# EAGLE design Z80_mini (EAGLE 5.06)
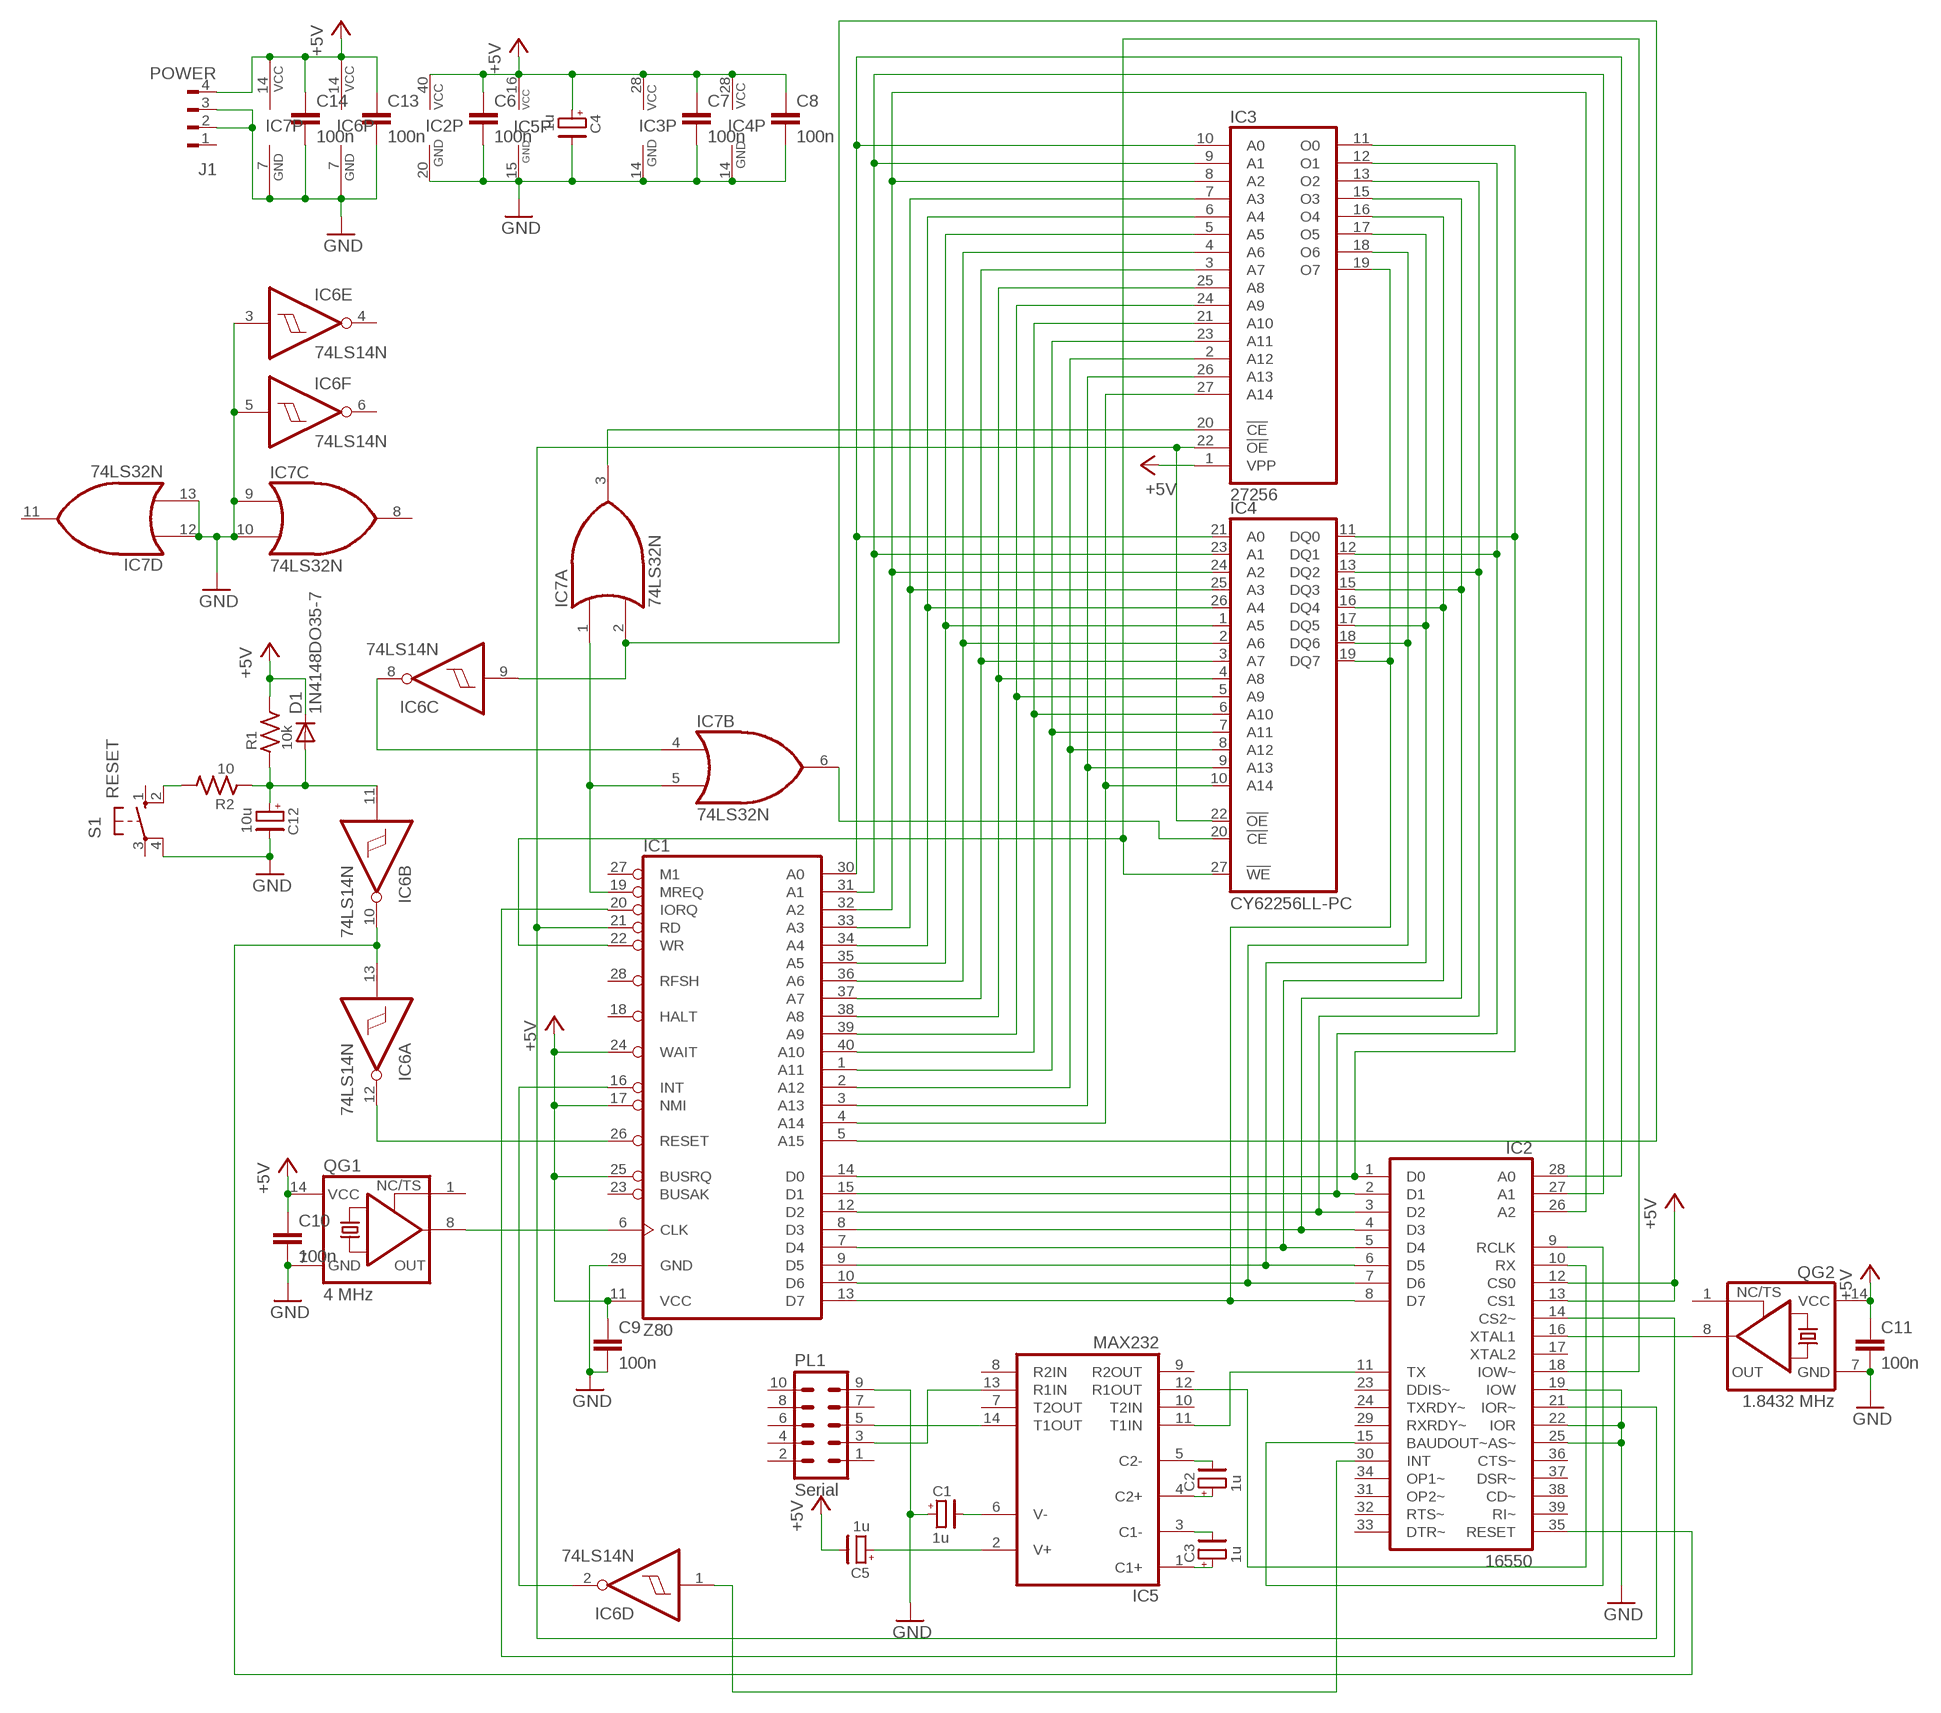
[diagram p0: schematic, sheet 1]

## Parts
C1  1u  CE01A  [CE01A]
C2  1u  CE01A  [CE01A]
C3  1u  CE01A  [CE01A]
C4  1u  CE01A  [CE01A]
C5  1u  CE01A  [CE01A]
C6  100n  C5/2.5  [C5B2.5]
C7  100n  C5/2.5  [C5B2.5]
C8  100n  C5/2.5  [C5B2.5]
C9  100n  C5/2.5  [C5B2.5]
C10  100n  C5/2.5  [C5B2.5]
C11  100n  C5/2.5  [C5B2.5]
C12  10u  CE01A  [CE01A]
C13  100n  C5/2.5  [C5B2.5]
C14  100n  C5/2.5  [C5B2.5]
D1  1N4148DO35-7  [DO35-7]
IC1  Z80  Z80CPU  [DIL40]
IC2  16550  XR-16C550P  [DIL40]
IC3  27256  [DIL28]
IC4  CY62256LL-PC  [DIL28-6]
IC5  MAX232  [DIL16]
IC6  74LS14N  [DIL14]
IC7  74LS32N  [DIL14]
J1  POWER  FLOPPY-4  [FLOPPY-4]
PL1  Serial  10H  [10H]
QG1  4 MHz  XO-14  [DIL14S]
QG2  1.8432 MHz  XO-14  [DIL14S]
R1  10k  RU  [R04N]
R2  10  RU  [R04N]
S1  RESET  10-XX  [B3F-10XX]

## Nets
+5V: C4.+ C5.- C6.1 C7.1 C8.1 C9.1 C10.1 C11.1 C13.1 C14.1 D1.C IC1.11(VCC) IC1.17(NMI) IC1.24(WAIT) IC1.25(BUSRQ) IC2.12(CS0) IC2.13(CS1) IC2.40(VCC) IC3.1(VPP) IC3.28(VCC) IC4.28(VCC) IC5.16(VCC) IC6.14(P:VCC) IC7.14(P:VCC) J1.4 QG1.14(VCC) QG2.14(VCC) R1.2
GND: C1.+ C4.- C6.2 C7.2 C8.2 C9.2 C10.2 C11.2 C12.- C13.2 C14.2 IC1.29(GND) IC2.19(IOW) IC2.20(GND) IC2.22(IOR) IC2.25(AS~) IC3.14(GND) IC4.14(GND) IC5.15(GND) IC6.3(E:I) IC6.5(F:I) IC6.7(P:GND) IC7.7(P:GND) IC7.9(C:I0) IC7.10(C:I1) IC7.12(D:I0) IC7.13(D:I1) J1.2 J1.3 PL1.9 QG1.7(GND) QG2.7(GND) S1.4(P1)
N$1: IC1.14(D0) IC2.1(D0) IC3.11(O0) IC4.11(DQ0)
N$2: IC1.15(D1) IC2.2(D1) IC3.12(O1) IC4.12(DQ1)
N$3: IC1.12(D2) IC2.3(D2) IC3.13(O2) IC4.13(DQ2)
N$4: IC1.8(D3) IC2.4(D3) IC3.15(O3) IC4.15(DQ3)
N$5: IC1.7(D4) IC2.5(D4) IC3.16(O4) IC4.16(DQ4)
N$6: IC1.9(D5) IC2.6(D5) IC3.17(O5) IC4.17(DQ5)
N$7: IC1.10(D6) IC2.7(D6) IC3.18(O6) IC4.18(DQ6)
N$8: IC1.13(D7) IC2.8(D7) IC3.19(O7) IC4.19(DQ7)
N$9: IC1.30(A0) IC2.28(A0) IC3.10(A0) IC4.21(A0)
N$10: IC1.31(A1) IC2.27(A1) IC3.9(A1) IC4.23(A1)
N$11: IC1.32(A2) IC2.26(A2) IC3.8(A2) IC4.24(A2)
N$12: IC1.33(A3) IC3.7(A3) IC4.25(A3)
N$13: IC1.34(A4) IC3.6(A4) IC4.26(A4)
N$14: IC1.35(A5) IC3.5(A5) IC4.1(A5)
N$15: IC1.36(A6) IC3.4(A6) IC4.2(A6)
N$16: IC1.37(A7) IC3.3(A7) IC4.3(A7)
N$17: IC1.38(A8) IC3.25(A8) IC4.4(A8)
N$18: IC1.39(A9) IC3.24(A9) IC4.5(A9)
N$19: IC1.40(A10) IC3.21(A10) IC4.6(A10)
N$20: IC1.1(A11) IC3.23(A11) IC4.7(A11)
N$21: IC1.2(A12) IC3.2(A12) IC4.8(A12)
N$22: IC1.3(A13) IC3.26(A13) IC4.9(A13)
N$23: IC1.4(A14) IC3.27(A14) IC4.10(A14)
N$24: IC2.11(TX) IC5.11(T1IN)
N$25: IC1.21(RD) IC2.21(IOR~) IC3.22(!OE) IC4.22(!OE)
N$26: IC1.22(WR) IC2.18(IOW~) IC4.27(!WE)
N$27: IC2.10(RX) IC5.12(R1OUT)
N$28: C1.- IC5.6(V-)
N$29: C2.- IC5.5(C2-)
N$30: C2.+ IC5.4(C2+)
N$31: C3.- IC5.3(C1-)
N$32: C3.+ IC5.1(C1+)
N$33: C5.+ IC5.2(V+)
N$34: IC5.14(T1OUT) PL1.5
N$35: IC5.13(R1IN) PL1.3
N$36: IC1.6(CLK) QG1.8(OUT)
N$37: IC1.26(RESET) IC6.12(A:O)
N$38: IC2.16(XTAL1) QG2.8(OUT)
N$39: IC2.9(RCLK) IC2.15(BAUDOUT~)
N$40: IC1.20(IORQ) IC2.14(CS2~)
N$41: IC2.35(RESET) IC6.10(B:O) IC6.13(A:I)
N$42: C12.+ D1.A IC6.11(B:I) R1.1 R2.1
N$43: R2.2 S1.2(S1)
N$44: IC1.19(MREQ) IC7.1(A:I0) IC7.5(B:I1)
N$46: IC3.20(!CE) IC7.3(A:O)
N$47: IC6.8(C:O) IC7.4(B:I0)
N$48: IC4.20(!CE) IC7.6(B:O)
N$49: IC2.30(INT) IC6.1(D:I)
N$50: IC1.16(INT) IC6.2(D:O)
N$52: IC1.5(A15) IC6.9(C:I) IC7.2(A:I1)
Unconnected: IC1.18(HALT) IC1.23(BUSAK) IC1.27(M1) IC1.28(RFSH) IC2.17(XTAL2) IC2.23(DDIS~) IC2.24(TXRDY~) IC2.29(RXRDY~) IC2.31(OP2~) IC2.32(RTS~) IC2.33(DTR~) IC2.34(OP1~) IC2.36(CTS~) IC2.37(DSR~) IC2.38(CD~) IC2.39(RI~) IC5.7(T2OUT) IC5.8(R2IN) IC5.9(R2OUT) IC5.10(T2IN) IC6.4(E:O) IC6.6(F:O) IC7.8(C:O) IC7.11(D:O) J1.1 PL1.1 PL1.2 PL1.4 PL1.6 PL1.7 PL1.8 PL1.10 QG1.1(TS) QG2.1(TS) S1.1(S) S1.3(P)

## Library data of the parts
C1-C5 C12 = divers:CE: Electrolytic capacitor
C6-C11 C13 C14 = capacitor-wima:C: CAPACITOR
D1 = diode:1N4148: DIODE
IC1 = zilog:Z80CPU: Z80 FAMILY DEVICE
IC2 = exar:XR-16C550P: UART/FIFO
IC3 = memory:27256: MEMORY
IC4 = memory-sram:CY62256LL-?*: 256K (32K x 8) CMOS-Static RAM Source: http://download.cypress.com.edgesuite.net/design_resources/datasheets/contents/cy62256_8.pdf
IC5 = maxim:MAX232: RS232 TRANSEIVER
IC6 = 74xx-us:74*14: Hex schmitt trigger INVERTER
IC7 = 74xx-us:74*32: Quad 2-input OR gate
J1 = con-amp:FLOPPY-4: MATE N-LOCK Floppy / HDD conector Distributor: Bürklin 71F970
PL1 = con-harting-h:10H: CONNECTOR
QG1 QG2 = crystal:XO-: CRYSTAL
R1 R2 = divers:RU: Resistor, US symbol
S1 = switch-omron:10-XX: OMRON SWITCH

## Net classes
0 +5V: width 0.508 mm

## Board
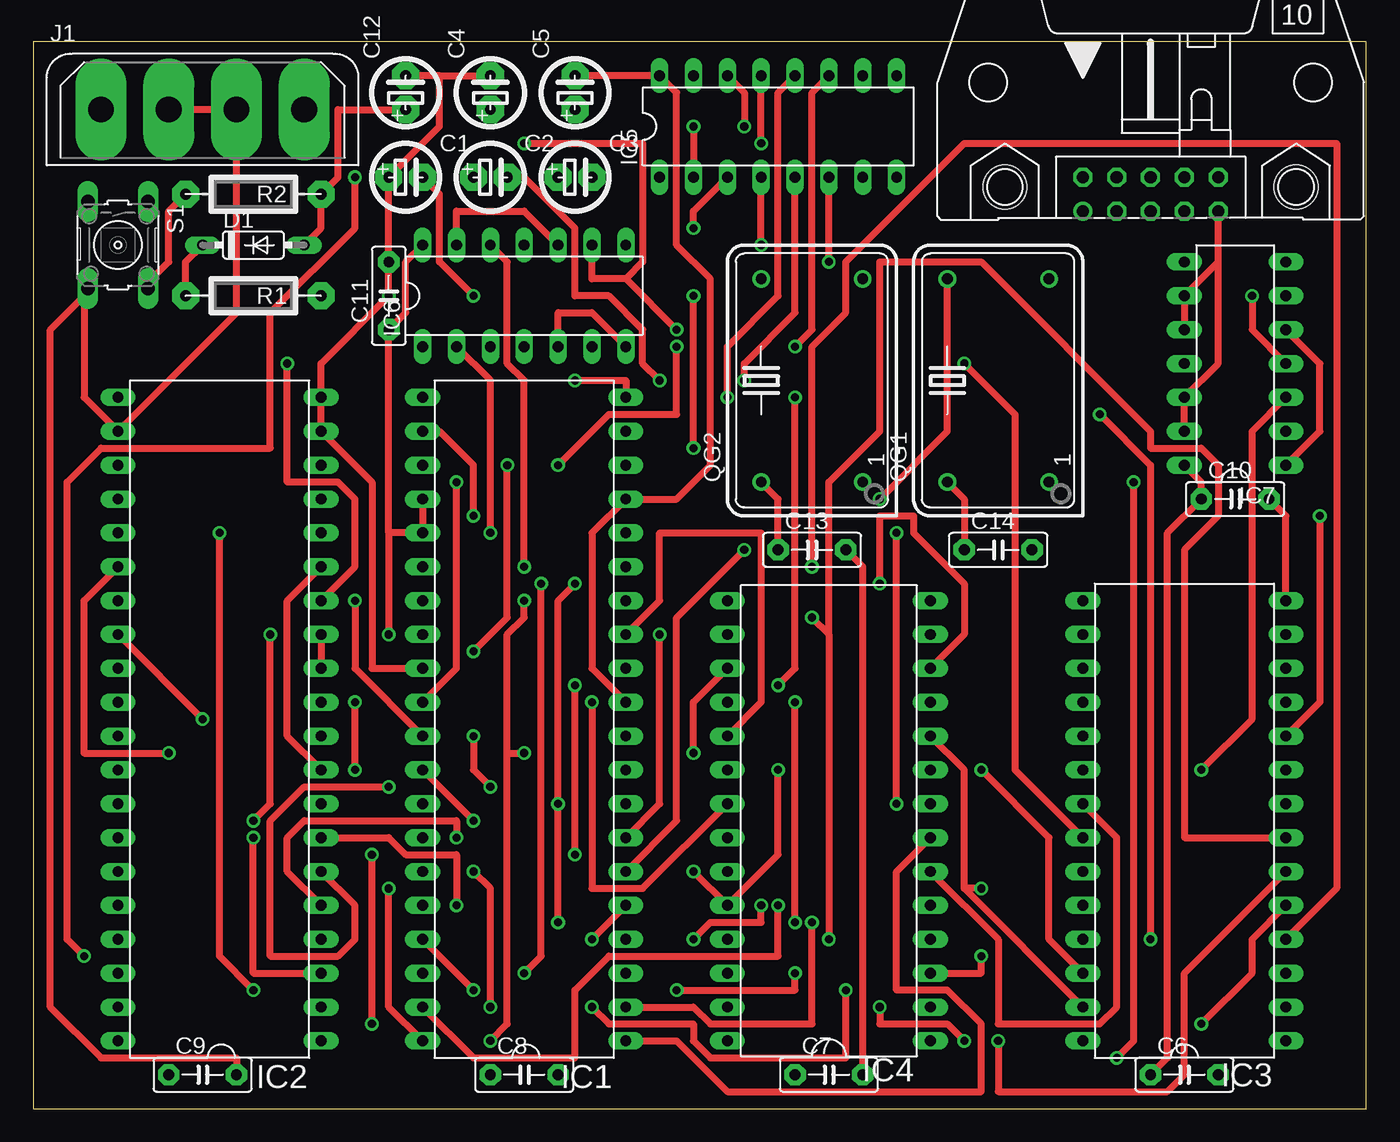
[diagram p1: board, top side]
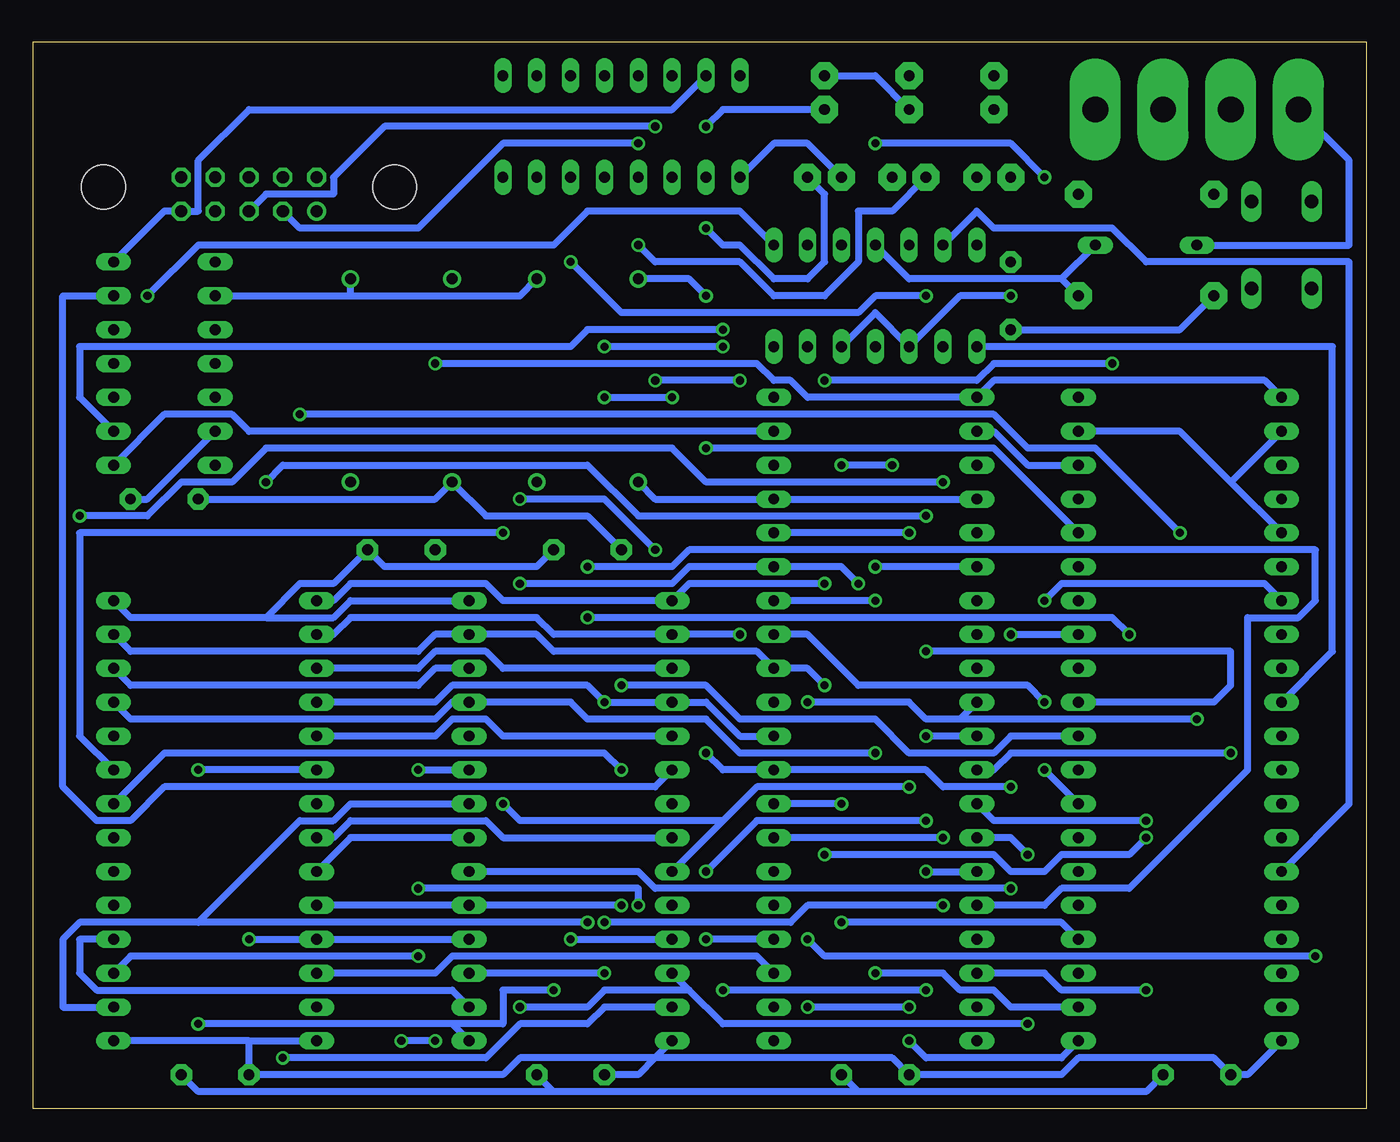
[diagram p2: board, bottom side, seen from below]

Size 100 x 80 mm. Coordinates in mm from the lower left corner, seen from the top.
Outline: 0,0 100,0 100,80 0,80 0,0
Copper layers (1*16): Top 0.035mm / dielectric 1.5mm / Bottom 0.035mm
Design rules "default *": minimum track width 20mil, minimum drill 24mil, track to track 8mil, track to pad 8mil, pad to pad 8mil, via to via 8mil, smd to smd 8mil, copper to edge 40mil, drill to drill 8mil, minimum pad ring 10mil, minimum via ring 8mil, stop-mask expansion 4mil, vias tented up to drill 0mil, thermal gap 10mil

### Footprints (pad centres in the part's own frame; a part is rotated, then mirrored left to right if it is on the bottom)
CE01A = drill 0.813 pad 2.032 octagon: + -1.27,0; - 1.27,0
C5B2.5 = drill 0.813 pad 1.6 octagon: 1 -2.54,0; 2 2.54,0
DO35-7 = drill 0.813 long: A 3.81,0; C -3.81,0
DIL40 = drill 0.813 long: 1 -24.13,-7.62; 2 -21.59,-7.62; 3 -19.05,-7.62; 4 -16.51,-7.62; 5 -13.97,-7.62; 6 -11.43,-7.62; 7 -8.89,-7.62; 8 -6.35,-7.62; 9 -3.81,-7.62; 10 -1.27,-7.62; 11 1.27,-7.62; 12 3.81,-7.62; 13 6.35,-7.62; 14 8.89,-7.62; 15 11.43,-7.62; 16 13.97,-7.62; 17 16.51,-7.62; 18 19.05,-7.62; 19 21.59,-7.62; 20 24.13,-7.62; 21 24.13,7.62; 22 21.59,7.62; 23 19.05,7.62; 24 16.51,7.62; 25 13.97,7.62; 26 11.43,7.62; 27 8.89,7.62; 28 6.35,7.62; 29 3.81,7.62; 30 1.27,7.62; 31 -1.27,7.62; 32 -3.81,7.62; 33 -6.35,7.62; 34 -8.89,7.62; 35 -11.43,7.62; 36 -13.97,7.62; 37 -16.51,7.62; 38 -19.05,7.62; 39 -21.59,7.62; 40 -24.13,7.62
DIL28 = drill 0.813 long: 1 -16.51,-7.62; 2 -13.97,-7.62; 3 -11.43,-7.62; 4 -8.89,-7.62; 5 -6.35,-7.62; 6 -3.81,-7.62; 7 -1.27,-7.62; 8 1.27,-7.62; 9 3.81,-7.62; 10 6.35,-7.62; 11 8.89,-7.62; 12 11.43,-7.62; 13 13.97,-7.62; 14 16.51,-7.62; 15 16.51,7.62; 16 13.97,7.62; 17 11.43,7.62; 18 8.89,7.62; 19 6.35,7.62; 20 3.81,7.62; 21 1.27,7.62; 22 -1.27,7.62; 23 -3.81,7.62; 24 -6.35,7.62; 25 -8.89,7.62; 26 -11.43,7.62; 27 -13.97,7.62; 28 -16.51,7.62
DIL28-6 = drill 0.813 long: 1 -16.51,-7.62; 2 -13.97,-7.62; 3 -11.43,-7.62; 4 -8.89,-7.62; 5 -6.35,-7.62; 6 -3.81,-7.62; 7 -1.27,-7.62; 8 1.27,-7.62; 9 3.81,-7.62; 10 6.35,-7.62; 11 8.89,-7.62; 12 11.43,-7.62; 13 13.97,-7.62; 14 16.51,-7.62; 15 16.51,7.62; 16 13.97,7.62; 17 11.43,7.62; 18 8.89,7.62; 19 6.35,7.62; 20 3.81,7.62; 21 1.27,7.62; 22 -1.27,7.62; 23 -3.81,7.62; 24 -6.35,7.62; 25 -8.89,7.62; 26 -11.43,7.62; 27 -13.97,7.62; 28 -16.51,7.62
DIL16 = drill 0.813 long: 1 -8.89,-3.81; 2 -6.35,-3.81; 3 -3.81,-3.81; 4 -1.27,-3.81; 5 1.27,-3.81; 6 3.81,-3.81; 7 6.35,-3.81; 8 8.89,-3.81; 9 8.89,3.81; 10 6.35,3.81; 11 3.81,3.81; 12 1.27,3.81; 13 -1.27,3.81; 14 -3.81,3.81; 15 -6.35,3.81; 16 -8.89,3.81
DIL14 = drill 0.813 long: 1 -7.62,-3.81; 2 -5.08,-3.81; 3 -2.54,-3.81; 4 0,-3.81; 5 2.54,-3.81; 6 5.08,-3.81; 7 7.62,-3.81; 8 7.62,3.81; 9 5.08,3.81; 10 2.54,3.81; 11 0,3.81; 12 -2.54,3.81; 13 -5.08,3.81; 14 -7.62,3.81
FLOPPY-4 = drill 1.93 pad 3.81 long: 1 7.62,0; 2 2.54,0; 3 -2.54,0; 4 -7.62,0
10H = drill 0.914 round: 1 -5.08,-1.27 | drill 0.914 octagon: 2 -5.08,1.27; 3 -2.54,-1.27; 4 -2.54,1.27; 5 0,-1.27; 6 0,1.27; 7 2.54,-1.27; 8 2.54,1.27; 9 5.08,-1.27; 10 5.08,1.27 | hole 3.302: -10.922,0.533; 10.922,0.533
DIL14S = drill 0.813 round: 1 -7.62,-3.81; 7 7.62,-3.81; 8 7.62,3.81; 14 -7.62,3.81
R04N = drill 0.813 pad 2.032 octagon: 1 -5.08,0; 2 5.08,0
B3F-10XX = drill 1.016 long: 1 -3.251,2.261; 2 3.251,2.261; 3 -3.251,-2.261; 4 3.251,-2.261

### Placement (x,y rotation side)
C1  27.94,69.85 0 top
C2  34.29,69.85 0 top
C3  40.64,69.85 0 top
C4  34.29,76.2 90 top
C5  40.64,76.2 90 top
C6  86.36,2.54 0 top
C7  59.69,2.54 0 top
C8  36.83,2.54 0 top
C9  12.7,2.54 0 top
C10  90.17,45.72 0 top
C11  26.67,60.96 90 top
C12  27.94,76.2 90 top
C13  58.42,41.91 0 top
C14  72.39,41.91 0 top
D1  16.51,64.77 0 top
IC1  36.83,29.21 90 top
IC2  13.97,29.21 90 top
IC3  86.36,21.59 90 top
IC4  59.69,21.59 90 top
IC5  55.88,73.66 0 top
IC6  36.83,60.96 0 top
IC7  90.17,55.88 90 top
J1  12.7,74.93 0 top
PL1  83.82,68.58 0 top
QG1  72.39,54.61 90 top
QG2  58.42,54.61 90 top
R1  16.51,60.96 180 top
R2  16.51,68.58 180 top
S1  6.35,64.77 270 top

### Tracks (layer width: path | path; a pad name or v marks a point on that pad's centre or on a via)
+5V  (via drill 0.61)
  Top 0.508: D1.C 11.43,63.5 R1.2 | IC1.24 IC1.25 26.67,43.18 | IC2.13 IC2.12 | IC6.14 27.94,63.5 27.94,59.69 C11.1 26.67,43.18 | 26.67,43.18 v26.67,35.56 | IC7.14 87.63,46.99 C10.1 85.09,43.18 85.09,3.81 C6.1 | QG1.14 69.85,45.72 C14.1 | C5.- IC5.16 48.26,76.2 48.26,64.77 50.8,62.23 50.8,48.26 48.26,45.72 IC1.17 41.91,43.18 41.91,33.02 IC1.11 | QG2.14 55.88,45.72 C13.1
  Bottom 0.508: 83.82,5.08 IC3.1 | 83.82,5.08 IC3.28 | 83.82,5.08 C6.1 64.77,2.54 63.5,3.81 53.34,3.81 | IC2.40 8.89,2.54 C9.1 11.43,3.81 21.59,3.81 22.86,2.54 C8.1 35.56,3.81 53.34,3.81 | 53.34,3.81 54.61,2.54 C7.1 | 53.34,3.81 IC4.28 | v26.67,35.56 IC2.13 | R1.2 13.97,58.42 C11.1 | J1.4 1.27,71.12 1.27,64.77 D1.C | C10.1 69.85,45.72 QG1.14 66.04,44.45 58.42,44.45 C13.1 | C4.+ 36.83,77.47 C5.- | QG2.14 53.34,45.72 IC1.17 IC1.24
GND  (via drill 0.61)
  Top 0.508: IC6.7 41.91,59.69 39.37,59.69 IC6.5 | 30.48,77.47 C4.- | 30.48,77.47 C12.- | 30.48,77.47 30.48,73.66 C1.+ C11.2 v26.67,60.96 21.59,55.88 IC2.20 IC2.19 25.4,46.99 25.4,33.02 IC1.29 | J1.3 J1.2 15.24,59.69 IC2.22 3.81,53.34 3.81,60.96 | IC7.13 IC7.12 88.9,55.88 88.9,63.5 | C10.2 93.98,44.45 IC3.14 | IC7.10 IC7.9 88.9,63.5 | 88.9,63.5 PL1.9 | C7.2 62.23,40.64 C13.2 | 3.81,60.96 1.27,58.42 1.27,7.62 5.08,3.81 15.24,3.81 C9.2 | 3.81,60.96 S1.4
  Bottom 0.508: IC6.5 36.83,59.69 IC6.3 30.48,60.96 v26.67,60.96 | 10.16,46.99 13.97,50.8 IC2.19 | 10.16,46.99 IC2.25 | IC2.22 10.16,46.99 | C9.2 16.51,1.27 38.1,1.27 | 38.1,1.27 C8.2 | 60.96,1.27 C7.2 | 38.1,1.27 60.96,1.27 | C6.2 87.63,1.27 60.96,1.27 | C13.2 62.23,40.64 73.66,40.64 C14.2 77.47,39.37 80.01,39.37 82.55,36.83 | IC4.14 76.2,38.1 77.47,36.83 82.55,36.83 | 82.55,36.83 92.71,36.83 IC3.14 | IC7.13 91.44,45.72 C10.2 | QG2.7 63.5,60.96 76.2,60.96 | IC7.9 76.2,60.96 | 76.2,60.96 QG1.7 | IC7.7 90.17,67.31 PL1.9 87.63,67.31 87.63,71.12 83.82,74.93 52.07,74.93 IC5.15
N$1  (via drill 0.61)
  Top 0.508: v34.29,5.08 35.56,6.35 35.56,26.67 | 35.56,26.67 35.56,35.56 36.83,36.83 v36.83,38.1 | 35.56,26.67 v36.83,26.67
  Bottom 0.508: IC3.11 92.71,29.21 69.85,29.21 68.58,30.48 IC4.11 59.69,30.48 58.42,29.21 49.53,29.21 46.99,26.67 v36.83,26.67 | IC2.1 22.86,3.81 33.02,3.81 v34.29,5.08 | v36.83,38.1 IC1.14
N$2  (via drill 0.61)
  Top 0.508: v36.83,10.16 38.1,11.43 v38.1,39.37 | IC4.12 69.85,35.56 69.85,39.37 66.04,43.18 66.04,44.45 63.5,44.45 v63.5,39.37
  Bottom 0.508: IC4.12 69.85,33.02 71.12,31.75 92.71,31.75 IC3.12 | IC2.2 26.67,7.62 27.94,8.89 30.48,8.89 31.75,10.16 v36.83,10.16 | v38.1,39.37 39.37,40.64 IC1.15 50.8,40.64 52.07,39.37 v63.5,39.37
N$3  (via drill 0.61)
  Top 0.508: IC2.3 16.51,10.16 v16.51,20.32 | v40.64,19.05 v40.64,31.75
  Bottom 0.508: v16.51,20.32 17.78,19.05 22.86,19.05 24.13,17.78 26.67,17.78 27.94,19.05 v40.64,19.05 | v40.64,31.75 41.91,33.02 IC1.12 45.72,34.29 60.96,34.29 62.23,35.56 IC4.13 69.85,35.56 71.12,34.29 92.71,34.29 IC3.13
N$4  (via drill 0.61)
  Top 0.508: v39.37,13.97 v39.37,22.86 39.37,38.1 v40.64,39.37
  Bottom 0.508: IC3.15 77.47,38.1 76.2,39.37 66.04,39.37 64.77,38.1 IC4.15 50.8,39.37 v40.64,39.37 | IC2.4 22.86,13.97 v39.37,13.97 | v39.37,22.86 IC1.8
N$5  (via drill 0.61)
  Top 0.508: IC2.5 19.05,17.78 19.05,20.32 20.32,21.59 31.75,21.59 v31.75,20.32 | v46.99,35.56 46.99,22.86 IC1.7
  Bottom 0.508: IC3.16 77.47,35.56 76.2,36.83 62.23,36.83 60.96,35.56 IC4.16 v46.99,35.56 | v31.75,20.32 IC1.7
N$6  (via drill 0.61)
  Top 0.508: IC2.6 24.13,15.24 24.13,12.7 22.86,11.43 17.78,11.43 17.78,21.59 20.32,24.13 v26.67,24.13 | IC4.17 49.53,30.48 v49.53,26.67
  Bottom 0.508: IC4.17 64.77,33.02 66.04,34.29 69.85,34.29 71.12,33.02 IC3.17 | v26.67,24.13 31.75,24.13 33.02,25.4 IC1.9 48.26,25.4 v49.53,26.67
N$7  (via drill 0.61)
  Top 0.508: IC2.7 26.67,20.32 27.94,19.05 31.75,19.05 v31.75,15.24 | v57.15,13.97 v57.15,30.48
  Bottom 0.508: v31.75,15.24 41.91,15.24 43.18,13.97 v57.15,13.97 | IC1.10 46.99,27.94 49.53,30.48 IC4.18 v57.15,30.48 58.42,31.75 68.58,31.75 69.85,30.48 IC3.18
N$8  (via drill 0.61)
  Top 0.508: v24.13,25.4 v24.13,30.48 | IC4.19 54.61,30.48 54.61,43.18 46.99,43.18 46.99,38.1 IC1.13
  Bottom 0.508: IC4.19 64.77,27.94 66.04,29.21 68.58,29.21 69.85,27.94 IC3.19 | IC2.8 v24.13,25.4 | v24.13,30.48 25.4,31.75 38.1,31.75 41.91,35.56 IC1.13
N$9  (via drill 0.61)
  Top 0.508: IC4.21 45.72,16.51 41.91,16.51 v41.91,30.48 | IC2.28 v12.7,29.21 | IC3.10 96.52,30.48 v96.52,44.45 | v31.75,46.99 31.75,33.02 IC1.30
  Bottom 0.508: v41.91,30.48 34.29,30.48 33.02,29.21 30.48,29.21 | 30.48,29.21 IC1.30 | v12.7,29.21 30.48,29.21 | v96.52,44.45 91.44,44.45 88.9,46.99 85.09,46.99 82.55,49.53 52.07,49.53 49.53,46.99 v31.75,46.99
N$10  (via drill 0.61)
  Top 0.508: IC1.31 24.13,33.02 v24.13,38.1 | v34.29,24.13 33.02,25.4 v33.02,27.94 | v64.77,22.86 v64.77,43.18
  Bottom 0.508: v24.13,38.1 22.86,39.37 7.62,39.37 IC2.27 | 48.26,21.59 45.72,24.13 v34.29,24.13 | 48.26,21.59 IC4.23 | IC1.31 v33.02,27.94 | IC3.9 96.52,27.94 96.52,43.18 v64.77,43.18 | v64.77,22.86 63.5,21.59 48.26,21.59
N$11  (via drill 0.61)
  Top 0.508: v10.16,26.67 3.81,26.67 3.81,38.1 IC2.26 | v55.88,25.4 55.88,19.05 IC4.24 v49.53,17.78 | IC1.32 v33.02,21.59
  Bottom 0.508: IC1.32 27.94,25.4 26.67,26.67 v10.16,26.67 | v55.88,25.4 57.15,26.67 90.17,26.67 IC3.8 | v33.02,21.59 45.72,21.59 v49.53,17.78
N$12  (via drill 0.61)
  Top 0.508: v16.51,21.59 17.78,22.86 v17.78,35.56 | v58.42,36.83 59.69,35.56 | 59.69,35.56 v59.69,12.7 | IC3.7 86.36,20.32 86.36,41.91 88.9,44.45 88.9,48.26 87.63,49.53 83.82,49.53 83.82,50.8 71.12,63.5 63.5,63.5 63.5,50.8 59.69,46.99 59.69,35.56
  Bottom 0.508: IC1.33 27.94,21.59 v16.51,21.59 | v17.78,35.56 19.05,36.83 v58.42,36.83 | v59.69,12.7 IC4.25
N$13  (via drill 0.61)
  Top 0.508: v25.4,6.35 v25.4,19.05 | IC3.6 86.36,10.16 86.36,2.54 85.09,1.27 72.39,1.27 v72.39,5.08 | v69.85,5.08 68.58,6.35 63.5,6.35 v63.5,7.62
  Bottom 0.508: IC1.34 26.67,20.32 v25.4,19.05 | v25.4,6.35 48.26,6.35 50.8,8.89 | 50.8,8.89 IC4.26 | v69.85,5.08 v72.39,5.08 | v63.5,7.62 58.42,7.62 57.15,8.89 50.8,8.89
N$14  (via drill 0.61)
  Top 0.508: v87.63,6.35 91.44,10.16 91.44,12.7 IC3.5 | v33.02,17.78 34.29,16.51 v34.29,7.62 | v41.91,7.62 43.18,6.35 49.53,6.35 49.53,5.08 50.8,3.81 60.96,3.81 v60.96,8.89
  Bottom 0.508: 68.58,6.35 IC4.1 | 68.58,6.35 v87.63,6.35 | v33.02,17.78 IC1.35 | v34.29,7.62 v41.91,7.62 | v60.96,8.89 64.77,8.89 64.77,6.35 68.58,6.35
N$15  (via drill 0.61)
  Top 0.508: v58.42,40.64 58.42,57.15 60.96,59.69 60.96,63.5 69.85,72.39 97.79,72.39 97.79,16.51 IC3.4
  Bottom 0.508: IC4.2 68.58,8.89 95.25,8.89 96.52,10.16 96.52,12.7 IC3.4 | IC1.36 24.13,15.24 22.86,16.51 17.78,16.51 8.89,25.4 8.89,36.83 5.08,36.83 3.81,38.1 3.81,41.91 50.8,41.91 52.07,40.64 v58.42,40.64
N$16  (via drill 0.61)
  Top 0.508: IC4.3 71.12,10.16 v71.12,11.43 | IC1.37 v33.02,8.89 | v48.26,8.89 57.15,8.89 v57.15,10.16
  Bottom 0.508: v71.12,11.43 92.71,11.43 IC3.3 | v33.02,8.89 v48.26,8.89 | v57.15,10.16 IC4.3
N$17  (via drill 0.61)
  Top 0.508: v16.51,8.89 13.97,11.43 v13.97,43.18 | v80.01,52.07 83.82,48.26 v83.82,12.7
  Bottom 0.508: IC1.38 24.13,10.16 22.86,8.89 v16.51,8.89 | v13.97,43.18 20.32,49.53 25.4,49.53 27.94,52.07 v80.01,52.07 | v83.82,12.7 IC3.25 IC4.4
N$18  (via drill 0.61)
  Top 0.508: IC1.39 33.02,3.81 40.64,3.81 40.64,8.89 43.18,11.43 55.88,11.43 v55.88,15.24
  Bottom 0.508: v55.88,15.24 IC4.5 IC3.24
N$19  (via drill 0.61)
  Top 0.508: IC1.40 26.67,7.62 v26.67,16.51 | IC3.21 81.28,20.32 81.28,7.62 80.01,6.35 72.39,6.35 72.39,12.7 IC4.6
  Bottom 0.508: v26.67,16.51 53.34,16.51 54.61,17.78 IC4.6
N$20
  Top 0.508: IC1.1 48.26,5.08 52.07,1.27 71.12,1.27 71.12,6.35 68.58,8.89 64.77,8.89 64.77,17.78 IC4.7
  Bottom 0.508: IC3.23 76.2,20.32 IC4.7
N$21  (via drill 0.61)
  Top 0.508: IC1.2 49.53,7.62 50.8,6.35 58.42,6.35 v58.42,13.97
  Bottom 0.508: 87.63,13.97 96.52,13.97 97.79,12.7 97.79,7.62 IC3.2 | v58.42,13.97 87.63,13.97 | IC4.8 76.2,22.86 77.47,21.59 80.01,21.59 87.63,13.97
N$22  (via drill 0.61)
  Top 0.508: v71.12,25.4 76.2,20.32 76.2,12.7 IC3.26
  Bottom 0.508: IC1.3 45.72,11.43 68.58,11.43 69.85,10.16 IC3.26 | v71.12,25.4 IC4.9
N$23  (via drill 0.61)
  Top 0.508: 69.85,16.51 IC3.27 | 69.85,16.51 69.85,25.4 IC4.10 | v49.53,12.7 50.8,13.97 54.61,13.97 v54.61,15.24 | v71.12,16.51 69.85,16.51
  Bottom 0.508: IC1.4 v49.53,12.7 | v54.61,15.24 54.61,16.51 v71.12,16.51
N$24  (via drill 0.61)
  Top 0.508: v33.02,34.29 35.56,36.83 v35.56,48.26 | v39.37,48.26 43.18,52.07 48.26,52.07 v48.26,57.15 | v57.15,57.15 58.42,58.42 58.42,76.2 IC5.11
  Bottom 0.508: IC2.11 11.43,30.48 10.16,31.75 10.16,34.29 v33.02,34.29 | v35.56,48.26 v39.37,48.26 | v48.26,57.15 v57.15,57.15
N$25  (via drill 0.61)
  Top 0.508: v69.85,55.88 73.66,52.07 73.66,25.4 IC3.22
  Bottom 0.508: IC2.21 7.62,54.61 27.94,54.61 IC1.21 41.91,53.34 43.18,54.61 44.45,54.61 45.72,55.88 v69.85,55.88 | IC4.22 64.77,20.32 66.04,21.59 76.2,21.59 77.47,20.32 IC3.22
N$26  (via drill 0.61)
  Top 0.508: v81.28,3.81 82.55,5.08 v82.55,46.99 | v33.02,44.45 33.02,48.26 30.48,50.8 IC1.22
  Bottom 0.508: IC2.18 25.4,48.26 27.94,50.8 IC1.22 | IC4.27 57.15,7.62 58.42,6.35 63.5,6.35 66.04,3.81 v81.28,3.81 | v82.55,46.99 81.28,48.26 58.42,48.26 54.61,44.45 v33.02,44.45
N$27  (via drill 0.61)
  Top 0.508: v55.88,31.75 57.15,33.02 v57.15,53.34 | v52.07,53.34 52.07,57.15 55.88,60.96 55.88,76.2 IC5.12
  Bottom 0.508: IC2.10 26.67,27.94 27.94,26.67 34.29,26.67 36.83,29.21 46.99,29.21 49.53,31.75 v55.88,31.75 | v57.15,53.34 v52.07,53.34
N$28  (via drill 0.61)
  Top 0.508: v59.69,63.5 IC5.6 | v33.02,60.96 30.48,63.5 30.48,68.58 C1.-
  Bottom 0.508: v59.69,63.5 55.88,59.69 38.1,59.69 36.83,60.96 v33.02,60.96
N$29  (via drill 0.61)
  Top 0.508: IC5.5 57.15,59.69 53.34,55.88 v53.34,54.61 | v46.99,54.61 45.72,55.88 45.72,58.42 43.18,60.96 40.64,60.96 40.64,66.04 36.83,69.85 C2.-
  Bottom 0.508: v46.99,54.61 v53.34,54.61
N$30  (via drill 0.61)
  Top 0.508: v54.61,64.77 IC5.4
  Bottom 0.508: v54.61,64.77 53.34,63.5 46.99,63.5 44.45,60.96 40.64,60.96 38.1,63.5 38.1,67.31 35.56,67.31 C2.+
N$31  (via drill 0.61)
  Top 0.508: IC5.3 49.53,67.31 v49.53,66.04
  Bottom 0.508: v49.53,66.04 48.26,64.77 46.99,64.77 44.45,62.23 41.91,62.23 40.64,63.5 40.64,68.58 C3.-
N$32
  Bottom 0.508: IC5.1 44.45,72.39 41.91,72.39 C3.+
N$33  (via drill 0.61)
  Top 0.508: v49.53,73.66 IC5.2
  Bottom 0.508: v49.53,73.66 48.26,74.93 C5.+
N$34  (via drill 0.61)
  Top 0.508: IC5.14 53.34,76.2 v53.34,73.66
  Bottom 0.508: v53.34,73.66 73.66,73.66 77.47,69.85 77.47,68.58 82.55,68.58 PL1.5
N$35  (via drill 0.61)
  Top 0.508: v54.61,72.39 IC5.13
  Bottom 0.508: v54.61,72.39 64.77,72.39 71.12,66.04 80.01,66.04 PL1.3
N$36  (via drill 0.61)
  Top 0.508: IC1.6 48.26,21.59 48.26,36.83 v53.34,41.91 | v63.5,45.72 68.58,50.8 QG1.8
  Bottom 0.508: v53.34,41.91 57.15,45.72 v63.5,45.72
N$37  (via drill 0.61)
  Top 0.508: v36.83,40.64 36.83,54.61 35.56,55.88 35.56,63.5 IC6.12
  Bottom 0.508: IC1.26 v36.83,40.64
N$38  (via drill 0.61)
  Top 0.508: v49.53,49.53 v49.53,60.96
  Bottom 0.508: IC2.16 27.94,49.53 v49.53,49.53 | v49.53,60.96 50.8,62.23 QG2.8
N$39
  Top 0.508: IC2.9 19.05,27.94 19.05,38.1 IC2.15
N$40  (via drill 0.61)
  Top 0.508: IC2.14 24.13,40.64 24.13,45.72 22.86,46.99 19.05,46.99 v19.05,55.88 | v40.64,54.61 44.45,54.61 IC1.20
  Bottom 0.508: v19.05,55.88 27.94,55.88 29.21,54.61 v40.64,54.61
N$41
  Top 0.508: IC6.10 36.83,67.31 31.75,67.31 IC6.13
  Bottom 0.508: IC2.35 1.27,22.86 1.27,63.5 16.51,63.5 19.05,66.04 27.94,66.04 29.21,67.31 IC6.13
N$42
  Top 0.508: D1.A 21.59,66.04 R2.1 22.86,69.85 22.86,74.93 C12.+
  Bottom 0.508: IC6.11 34.29,62.23 22.86,62.23 | R1.1 22.86,62.23 | 22.86,62.23 D1.A
N$43
  Top 0.508: R2.2 10.16,67.31 10.16,63.5 8.89,62.23 S1.2
N$44
  Top 0.508: IC7.1 96.52,50.8 96.52,55.88 IC7.5
  Bottom 0.508: IC1.19 83.82,50.8 85.09,52.07 90.17,52.07 IC7.1
N$46  (via drill 0.61)
  Top 0.508: v87.63,25.4 91.44,29.21 91.44,50.8 IC7.3
  Bottom 0.508: IC3.20 v87.63,25.4
N$47  (via drill 0.61)
  Top 0.508: IC7.4 91.44,58.42 v91.44,60.96
  Bottom 0.508: v91.44,60.96 87.63,64.77 60.96,64.77 58.42,67.31 46.99,67.31 IC6.8
N$48
  Bottom 0.508: IC4.20 53.34,24.13 90.17,24.13 92.71,21.59 95.25,21.59 97.79,24.13 97.79,60.96 IC7.6
N$49
  Bottom 0.508: IC2.30 2.54,34.29 2.54,57.15 IC6.1
N$50  (via drill 0.61)
  Top 0.508: IC6.2 34.29,54.61 v34.29,43.18
  Bottom 0.508: v34.29,43.18 IC1.16
N$52  (via drill 0.61)
  Top 0.508: v41.91,12.7 IC1.5 | v3.81,11.43 2.54,12.7 2.54,46.99 5.08,49.53 17.78,49.53 17.78,59.69 24.13,66.04 v24.13,69.85 | v36.83,72.39 45.72,72.39 45.72,63.5 44.45,62.23 | 44.45,62.23 41.91,62.23 IC6.9 | 44.45,62.23 v48.26,58.42
  Bottom 0.508: v41.91,12.7 40.64,11.43 v3.81,11.43 | v24.13,69.85 26.67,72.39 v36.83,72.39 | IC7.2 96.52,53.34 96.52,57.15 59.69,57.15 58.42,58.42 v48.26,58.42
